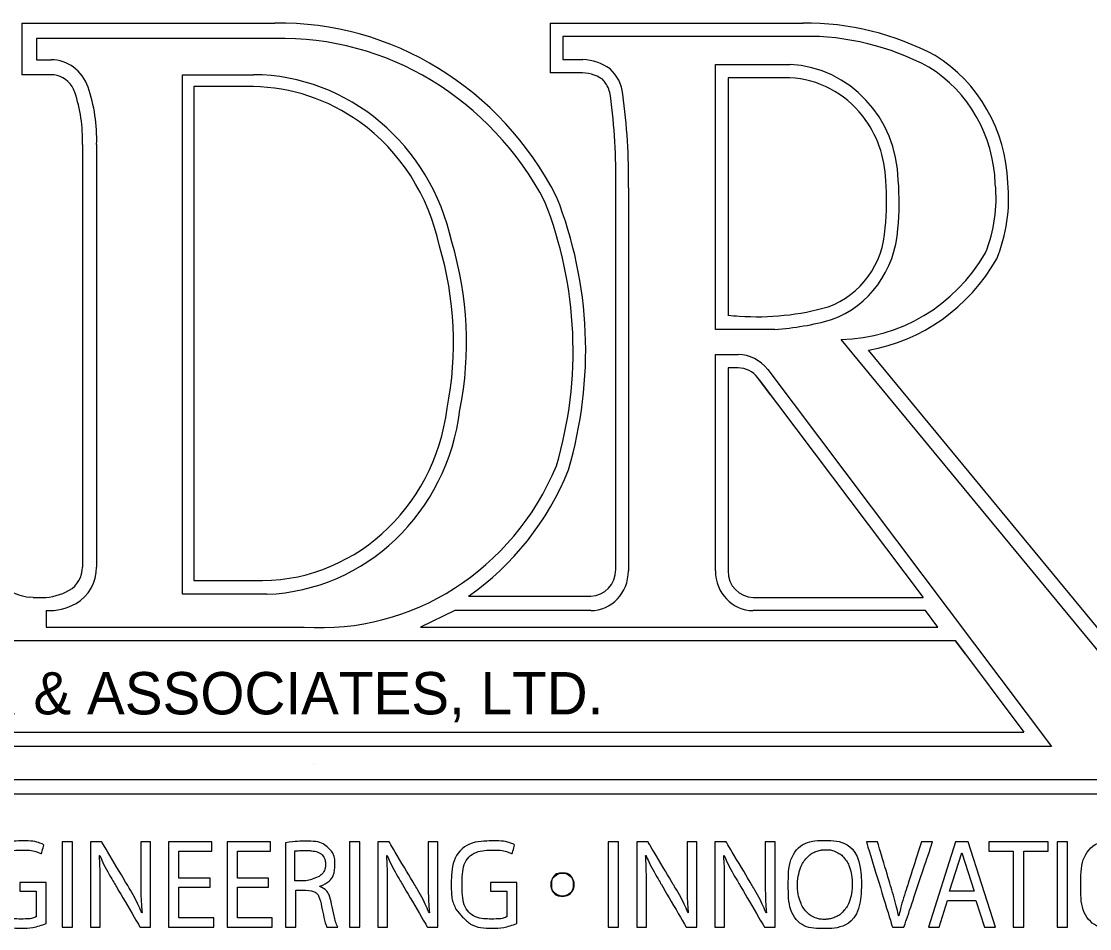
# Model space of a CAD drawing. Extents: x 0 to 34, y 0 to 22.
# Drawn here: x 32.53 to 33.336, y 3.375 to 4.06 of the extents above; entities that cross this region are included whole.
import ezdxf

# ---------------------------------------------------------------- set-up
doc = ezdxf.new("R2010")
doc.units = 0
doc.layers.add('SH_Data', color=7, linetype='Continuous')

msp = doc.modelspace()

# ---------------------------------------------------------------- linework, layer by layer
at = {"layer": 'SH_Data'}
for p, q in [((32.52996, 4.059), (32.52996, 4.02001)), ((32.52996, 4.059), (32.72096, 4.059)), ((32.92896, 4.059), (32.92896, 4.02146)), ((32.92896, 4.059), (33.11996, 4.059)), ((32.92896, 4.059), (32.92896, 4.02146)), ((32.92896, 4.059), (33.11996, 4.059)), ((32.54419, 4.02001), (32.52996, 4.02001)), ((32.55198, 4.02001), (32.54419, 4.02001)), ((32.94319, 4.02146), (32.92896, 4.02146)), ((32.94319, 4.02146), (32.92896, 4.02146)), ((32.95098, 4.02146), (32.94319, 4.02146)), ((32.70486, 4.01101), (32.65976, 4.01101)), ((32.65976, 4.01101), (32.65976, 3.63792)), ((32.57566, 3.96729), (32.57566, 3.64811)), ((32.97852, 3.64621), (32.97852, 3.93474)), ((33.38489, 3.55057), (33.16923, 3.81191)), ((33.08681, 3.78957), (33.2106, 3.62519)), ((32.65976, 3.63792), (32.66831, 3.63792)), ((32.66831, 3.63792), (32.70486, 3.63792)), ((32.53838, 3.62516), (32.53558, 3.62542)), ((32.53838, 3.62516), (32.53558, 3.62542)), ((32.53838, 3.62516), (32.54534, 3.62516)), ((32.86732, 3.62621), (32.95952, 3.62621)), ((33.08223, 3.62519), (33.2106, 3.62519)), ((33.23507, 3.59224), (33.28673, 3.52336)), ((32.21118, 3.52336), (33.28673, 3.52336)), ((32.75, 3.5), (32.75, 3.5)), ((33.44039, 3.47664), (32.07007, 3.47664)), ((32.7567, 3.4307), (32.75677, 3.43063)), ((33.2306, 3.40329), (33.23982, 3.43225)), ((33.23982, 3.43225), (33.24908, 3.40329)), ((32.75255, 3.4136), (32.74792, 3.41193)), ((32.73689, 3.41095), (32.73609, 3.41095)), ((32.74792, 3.41193), (32.74453, 3.41095)), ((32.75492, 3.40673), (32.75492, 3.40702)), ((33.24908, 3.40329), (33.2306, 3.40329)), ((32.76039, 3.376), (32.76847, 3.376))]:
    msp.add_line(p, q, dxfattribs=at)
for points in [[(32.72096, 4.04743), (32.54097, 4.04743), (32.54097, 4.03132), (32.55198, 4.03132)], [(33.11996, 4.049), (32.93846, 4.049), (32.93846, 4.03146), (32.95356, 4.03146)], [(33.05373, 4.02776), (33.11024, 4.02776)], [(33.09871, 3.82764), (33.05373, 3.82764), (33.05373, 4.02776)], [(32.65139, 3.62757), (32.65139, 4.02001), (32.70486, 4.02001)], [(33.11001, 4.01776), (33.06323, 4.01776), (33.06323, 3.83841)], [(32.58641, 3.96729), (32.58641, 3.96683), (32.58641, 3.64811)], [(32.98802, 3.93464), (32.98802, 3.64519)], [(33.37719, 3.54313), (33.14872, 3.82)], [(33.05373, 3.64519), (33.05373, 3.80857), (33.07085, 3.80857)], [(33.09319, 3.79721), (33.30749, 3.51264), (32.20382, 3.51264)], [(33.07085, 3.79857), (33.06323, 3.79857), (33.06323, 3.64519)], [(33.09537, 3.77821), (33.08574, 3.791)], [(32.71502, 3.62757), (32.65139, 3.62757)], [(32.86732, 3.62621), (32.88937, 3.62621)], [(33.08223, 3.62519), (33.08603, 3.62519)], [(32.54836, 3.61524), (32.54836, 3.60274), (32.74315, 3.60274)], [(32.95952, 3.61519), (32.85698, 3.61519), (32.83108, 3.60274), (33.22168, 3.60274), (33.21235, 3.61519), (33.08223, 3.61519)], [(33.24257, 3.58224), (33.23507, 3.59224), (32.24118, 3.59224), (32.20224, 3.52719)], [(32.06602, 3.50059), (32.06602, 3.48764), (33.42994, 3.48764), (33.42994, 3.50061)], [(32.72909, 3.43966), (32.72909, 3.376), (32.73689, 3.376), (32.73689, 3.40395), (32.74425, 3.40395)], [(33.25036, 3.39629), (33.25682, 3.376), (33.26516, 3.376), (33.24452, 3.44052), (33.23511, 3.44052), (33.21456, 3.376), (33.22263, 3.376), (33.22891, 3.39629), (33.25036, 3.39629)], [(32.74453, 3.41095), (32.74439, 3.41095), (32.74425, 3.41095)]]:
    msp.add_lwpolyline(points, dxfattribs=at)
msp.add_circle((32.93824, 3.40825), 0.00867, dxfattribs=at)
for centre, major_axis, start_param, end_param in [((32.72433, 3.80818), (0, 0.25085), 5.209873, 6.297313), ((33.12226, 3.8329), (0, 0.22611), 5.810103, 6.294452), ((33.12226, 3.8329), (0, 0.22611), 5.810103, 6.294452), ((32.72602, 3.80812), (0, 0.23937), 5.218006, 6.305445), ((33.12243, 3.83351), (0, 0.21551), 5.814829, 6.29527), ((33.16379, 3.93362), (0, 0.11672), 4.753214, 5.755325), ((33.16379, 3.93362), (0, 0.11672), 4.753214, 5.755325), ((32.55198, 4.00001), (0, 0.03131), 5.060756, 6.283185), ((32.95218, 3.98966), (0, 0.04182), 5.696071, 6.248499), ((33.10631, 3.93781), (0, 0.09005), 4.740194, 6.23721), ((33.16379, 3.93362), (0, 0.10672), 4.750292, 5.755325), ((32.55198, 4.00001), (0, 0.02), 5.294753, 6.283185), ((32.70388, 3.8572), (0, 0.16282), 4.938334, 6.276888), ((32.95218, 3.98966), (0, 0.03182), 5.717883, 6.322951), ((32.95511, 4.00164), (0, 0.03041), 4.832872, 5.561833), ((33.10631, 3.93781), (0, 0.08005), 5.402738, 6.234422), ((32.55198, 4.00001), (0, 0.02), 5.060756, 5.294753), ((32.47755, 3.97156), (0, 0.11467), 4.675194, 5.060756), ((32.70276, 3.85737), (0, 0.15366), 5.684676, 6.268828), ((32.95511, 4.00164), (0, 0.02041), 5.34604, 5.529903), ((32.95511, 4.00164), (0, 0.02041), 4.827568, 5.34604), ((32.95511, 4.00164), (0, 0.02041), 4.827568, 5.34604), ((32.47755, 3.97156), (0, 0.10336), 4.671123, 5.060756), ((32.57484, 3.94271), (0, 0.425), 4.693619, 4.857063), ((32.57484, 3.94271), (0, 0.425), 4.693619, 4.857063), ((32.57484, 3.94271), (0, 0.435), 4.693836, 4.856756), ((33.10631, 3.93781), (0, 0.08005), 4.740194, 5.402738), ((33.10631, 3.93781), (0, 0.08005), 4.740194, 5.402738), ((32.70276, 3.85737), (0, 0.15366), 4.930275, 5.684676), ((33.00347, 3.92393), (0, 0.18895), 4.608112, 4.797709), ((33.00347, 3.92393), (0, 0.18895), 4.608112, 4.797709), ((33.00861, 3.92385), (0, 0.19356), 4.607961, 4.797558), ((33.16601, 3.92655), (0, 0.10489), 4.309756, 4.818512), ((33.16601, 3.92655), (0, 0.11489), 4.303317, 4.815541), ((33.16601, 3.92655), (0, 0.11489), 4.303317, 4.815541), ((32.66751, 3.81165), (0, 0.2934), 4.410917, 5.105556), ((32.66751, 3.81165), (0, 0.3034), 4.410917, 5.105556), ((33.11824, 3.90826), (0, -0.06723), 0.330696, 1.511334), ((33.11824, 3.90826), (0, -0.06723), 0.330696, 1.511334), ((33.11779, 3.90865), (0, -0.07773), 0.32607, 1.506707), ((32.62458, 3.81762), (0, 0.24352), 4.507644, 5.016706), ((32.62601, 3.8177), (0, 0.25236), 4.509144, 5.018206), ((33.14666, 3.95705), (0, -0.13706), 0.015856, 1.021186), ((33.14666, 3.95705), (0, -0.14706), 0.16231, 1.026165), ((33.14666, 3.95705), (0, -0.14706), 0.16231, 1.026165), ((33.08509, 4.05603), (0, -0.21884), 6.219099, 6.545404), ((33.08509, 4.05603), (0, -0.21884), 6.219099, 6.545404), ((33.08509, 4.05603), (0, -0.21884), 6.177822, 6.219099), ((33.08509, 4.05603), (0, -0.22884), 0.06267, 0.262218), ((33.07085, 3.77857), (0, 0.03), 5.382662, 6.283185), ((33.07085, 3.77857), (0, 0.02), 5.382662, 6.283185), ((32.70994, 3.78768), (0, -0.14986), 6.247489, 7.723), ((32.70994, 3.78768), (0, -0.16019), 0.033392, 1.439815), ((32.75571, 3.80698), (0, -0.20467), 6.218561, 7.439351), ((32.75561, 3.80484), (0, -0.21386), 0.582172, 1.170799), ((32.55666, 3.64811), (0, -0.02), 0.497877, 1.570796), ((32.55666, 3.64811), (0, -0.03132), 0.497877, 1.570796), ((32.95952, 3.64621), (0, -0.02), 0, 1.570796), ((32.95952, 3.64519), (0, -0.03), 0, 1.570796), ((33.08223, 3.64519), (0, -0.03), 4.712389, 6.283185), ((33.08223, 3.64519), (0, -0.02), 4.712389, 6.283185), ((32.54013, 3.66951), (0, -0.04436), 5.785308, 6.174936), ((32.54561, 3.66951), (0, -0.04436), 6.276852, 6.781063), ((32.5506, 3.65985), (0, -0.04467), 6.230381, 6.780961)]:
    msp.add_ellipse(centre, major_axis=major_axis, ratio=0.95, start_param=start_param, end_param=end_param, dxfattribs=at)
for points, degree in [([(32.54839, 3.37887), (32.54489, 3.37753), (32.53798, 3.37533), (32.52982, 3.37533), (32.52067, 3.37533), (32.51313, 3.37782), (32.50721, 3.38385), (32.50201, 3.38921), (32.49878, 3.39783), (32.49878, 3.40788), (32.49887, 3.42712), (32.51125, 3.44119), (32.53152, 3.44119), (32.53852, 3.44119), (32.54399, 3.43956), (32.5466, 3.43822), (32.5466, 3.43822), (32.54471, 3.43142), (32.54471, 3.43142), (32.54148, 3.43295), (32.53745, 3.4342), (32.53134, 3.4342), (32.51663, 3.4342), (32.50703, 3.42444), (32.50703, 3.40826), (32.50703, 3.39189), (32.51627, 3.38222), (32.53036, 3.38222), (32.53547, 3.38222), (32.53897, 3.38299), (32.54077, 3.38395), (32.54077, 3.38395), (32.54077, 3.40319), (32.54077, 3.40319), (32.54077, 3.40319), (32.52847, 3.40319), (32.52847, 3.40319), (32.52847, 3.40319), (32.52847, 3.40989), (32.52847, 3.40989), (32.52847, 3.40989), (32.54839, 3.40989), (32.54839, 3.40989), (32.54839, 3.40989), (32.54839, 3.37887), (32.54839, 3.37887)], 3), ([(32.56813, 3.44052), (32.56813, 3.44052), (32.56813, 3.376), (32.56813, 3.376), (32.56813, 3.376), (32.56032, 3.376), (32.56032, 3.376), (32.56032, 3.376), (32.56032, 3.44052), (32.56032, 3.44052), (32.56032, 3.44052), (32.56813, 3.44052), (32.56813, 3.44052)], 3), ([(32.58177, 3.376), (32.58177, 3.376), (32.58177, 3.44052), (32.58177, 3.44052), (32.58177, 3.44052), (32.59029, 3.44052), (32.59029, 3.44052), (32.59029, 3.44052), (32.60967, 3.40788), (32.60967, 3.40788), (32.61416, 3.40031), (32.61766, 3.39352), (32.62053, 3.38691), (32.62053, 3.38691), (32.62071, 3.38701), (32.62071, 3.38701), (32.61999, 3.39562), (32.61981, 3.40347), (32.61981, 3.41352), (32.61981, 3.41352), (32.61981, 3.44052), (32.61981, 3.44052), (32.61981, 3.44052), (32.62717, 3.44052), (32.62717, 3.44052), (32.62717, 3.44052), (32.62717, 3.376), (32.62717, 3.376), (32.62717, 3.376), (32.61927, 3.376), (32.61927, 3.376), (32.61927, 3.376), (32.60007, 3.40874), (32.60007, 3.40874), (32.59585, 3.41592), (32.59182, 3.42329), (32.58876, 3.43027), (32.58876, 3.43027), (32.5885, 3.43018), (32.5885, 3.43018), (32.58894, 3.42204), (32.58912, 3.41429), (32.58912, 3.40357), (32.58912, 3.40357), (32.58912, 3.376), (32.58912, 3.376), (32.58912, 3.376), (32.58177, 3.376), (32.58177, 3.376)], 3), ([(32.67211, 3.40625), (32.67211, 3.40625), (32.64861, 3.40625), (32.64861, 3.40625), (32.64861, 3.40625), (32.64861, 3.38299), (32.64861, 3.38299), (32.64861, 3.38299), (32.67481, 3.38299), (32.67481, 3.38299), (32.67481, 3.38299), (32.67481, 3.376), (32.67481, 3.376), (32.67481, 3.376), (32.6408, 3.376), (32.6408, 3.376), (32.6408, 3.376), (32.6408, 3.44052), (32.6408, 3.44052), (32.6408, 3.44052), (32.67346, 3.44052), (32.67346, 3.44052), (32.67346, 3.44052), (32.67346, 3.43353), (32.67346, 3.43353), (32.67346, 3.43353), (32.64861, 3.43353), (32.64861, 3.43353), (32.64861, 3.43353), (32.64861, 3.41314), (32.64861, 3.41314), (32.64861, 3.41314), (32.67211, 3.41314), (32.67211, 3.41314), (32.67211, 3.41314), (32.67211, 3.40625), (32.67211, 3.40625)], 3), ([(32.71626, 3.40625), (32.71626, 3.40625), (32.69275, 3.40625), (32.69275, 3.40625), (32.69275, 3.40625), (32.69275, 3.38299), (32.69275, 3.38299), (32.69275, 3.38299), (32.71895, 3.38299), (32.71895, 3.38299), (32.71895, 3.38299), (32.71895, 3.376), (32.71895, 3.376), (32.71895, 3.376), (32.68494, 3.376), (32.68494, 3.376), (32.68494, 3.376), (32.68494, 3.44052), (32.68494, 3.44052), (32.68494, 3.44052), (32.7176, 3.44052), (32.7176, 3.44052), (32.7176, 3.44052), (32.7176, 3.43353), (32.7176, 3.43353), (32.7176, 3.43353), (32.69275, 3.43353), (32.69275, 3.43353), (32.69275, 3.43353), (32.69275, 3.41314), (32.69275, 3.41314), (32.69275, 3.41314), (32.71626, 3.41314), (32.71626, 3.41314), (32.71626, 3.41314), (32.71626, 3.40625), (32.71626, 3.40625)], 3), ([(32.75492, 3.40702), (32.76129, 3.40931), (32.76632, 3.41496), (32.76632, 3.42348), (32.76632, 3.42846), (32.76461, 3.43286), (32.76156, 3.43573), (32.7578, 3.43937), (32.75241, 3.44099), (32.74407, 3.44099), (32.73869, 3.44099), (32.73303, 3.44052), (32.72909, 3.43966)], 3), ([(32.78516, 3.44052), (32.78516, 3.44052), (32.78516, 3.376), (32.78516, 3.376), (32.78516, 3.376), (32.77735, 3.376), (32.77735, 3.376), (32.77735, 3.376), (32.77735, 3.44052), (32.77735, 3.44052), (32.77735, 3.44052), (32.78516, 3.44052), (32.78516, 3.44052)], 3), ([(32.79879, 3.376), (32.79879, 3.376), (32.79879, 3.44052), (32.79879, 3.44052), (32.79879, 3.44052), (32.80732, 3.44052), (32.80732, 3.44052), (32.80732, 3.44052), (32.8267, 3.40788), (32.8267, 3.40788), (32.83118, 3.40031), (32.83468, 3.39352), (32.83755, 3.38691), (32.83755, 3.38691), (32.83774, 3.38701), (32.83774, 3.38701), (32.83702, 3.39562), (32.83684, 3.40347), (32.83684, 3.41352), (32.83684, 3.41352), (32.83684, 3.44052), (32.83684, 3.44052), (32.83684, 3.44052), (32.84419, 3.44052), (32.84419, 3.44052), (32.84419, 3.44052), (32.84419, 3.376), (32.84419, 3.376), (32.84419, 3.376), (32.8363, 3.376), (32.8363, 3.376), (32.8363, 3.376), (32.8171, 3.40874), (32.8171, 3.40874), (32.81288, 3.41592), (32.80884, 3.42329), (32.80579, 3.43027), (32.80579, 3.43027), (32.80552, 3.43018), (32.80552, 3.43018), (32.80597, 3.42204), (32.80615, 3.41429), (32.80615, 3.40357), (32.80615, 3.40357), (32.80615, 3.376), (32.80615, 3.376), (32.80615, 3.376), (32.79879, 3.376), (32.79879, 3.376)], 3), ([(32.90386, 3.37887), (32.90036, 3.37753), (32.89345, 3.37533), (32.88529, 3.37533), (32.87613, 3.37533), (32.8686, 3.37782), (32.86267, 3.38385), (32.85747, 3.38921), (32.85424, 3.39783), (32.85424, 3.40788), (32.85433, 3.42712), (32.86671, 3.44119), (32.88699, 3.44119), (32.89399, 3.44119), (32.89946, 3.43956), (32.90206, 3.43822), (32.90206, 3.43822), (32.90018, 3.43142), (32.90018, 3.43142), (32.89695, 3.43295), (32.89291, 3.4342), (32.88681, 3.4342), (32.8721, 3.4342), (32.8625, 3.42444), (32.8625, 3.40826), (32.8625, 3.39189), (32.87174, 3.38222), (32.88582, 3.38222), (32.89094, 3.38222), (32.89444, 3.38299), (32.89623, 3.38395), (32.89623, 3.38395), (32.89623, 3.40319), (32.89623, 3.40319), (32.89623, 3.40319), (32.88394, 3.40319), (32.88394, 3.40319), (32.88394, 3.40319), (32.88394, 3.40989), (32.88394, 3.40989), (32.88394, 3.40989), (32.90386, 3.40989), (32.90386, 3.40989), (32.90386, 3.40989), (32.90386, 3.37887), (32.90386, 3.37887)], 3), ([(32.98065, 3.44052), (32.98065, 3.44052), (32.98065, 3.376), (32.98065, 3.376), (32.98065, 3.376), (32.97285, 3.376), (32.97285, 3.376), (32.97285, 3.376), (32.97285, 3.44052), (32.97285, 3.44052), (32.97285, 3.44052), (32.98065, 3.44052), (32.98065, 3.44052)], 3), ([(32.99429, 3.376), (32.99429, 3.376), (32.99429, 3.44052), (32.99429, 3.44052), (32.99429, 3.44052), (33.00282, 3.44052), (33.00282, 3.44052), (33.00282, 3.44052), (33.02219, 3.40788), (33.02219, 3.40788), (33.02668, 3.40031), (33.03018, 3.39352), (33.03305, 3.38691), (33.03305, 3.38691), (33.03323, 3.38701), (33.03323, 3.38701), (33.03251, 3.39562), (33.03234, 3.40347), (33.03234, 3.41352), (33.03234, 3.41352), (33.03234, 3.44052), (33.03234, 3.44052), (33.03234, 3.44052), (33.03969, 3.44052), (33.03969, 3.44052), (33.03969, 3.44052), (33.03969, 3.376), (33.03969, 3.376), (33.03969, 3.376), (33.03179, 3.376), (33.03179, 3.376), (33.03179, 3.376), (33.01259, 3.40874), (33.01259, 3.40874), (33.00838, 3.41592), (33.00434, 3.42329), (33.00129, 3.43027), (33.00129, 3.43027), (33.00102, 3.43018), (33.00102, 3.43018), (33.00147, 3.42204), (33.00165, 3.41429), (33.00165, 3.40357), (33.00165, 3.40357), (33.00165, 3.376), (33.00165, 3.376), (33.00165, 3.376), (32.99429, 3.376), (32.99429, 3.376)], 3), ([(33.05333, 3.376), (33.05333, 3.376), (33.05333, 3.44052), (33.05333, 3.44052), (33.05333, 3.44052), (33.06185, 3.44052), (33.06185, 3.44052), (33.06185, 3.44052), (33.08123, 3.40788), (33.08123, 3.40788), (33.08572, 3.40031), (33.08922, 3.39352), (33.09209, 3.38691), (33.09209, 3.38691), (33.09227, 3.38701), (33.09227, 3.38701), (33.09155, 3.39562), (33.09137, 3.40347), (33.09137, 3.41352), (33.09137, 3.41352), (33.09137, 3.44052), (33.09137, 3.44052), (33.09137, 3.44052), (33.09873, 3.44052), (33.09873, 3.44052), (33.09873, 3.44052), (33.09873, 3.376), (33.09873, 3.376), (33.09873, 3.376), (33.09083, 3.376), (33.09083, 3.376), (33.09083, 3.376), (33.07163, 3.40874), (33.07163, 3.40874), (33.06742, 3.41592), (33.06338, 3.42329), (33.06033, 3.43027), (33.06033, 3.43027), (33.06006, 3.43018), (33.06006, 3.43018), (33.0605, 3.42204), (33.06069, 3.41429), (33.06069, 3.40357), (33.06069, 3.40357), (33.06069, 3.376), (33.06069, 3.376), (33.06069, 3.376), (33.05333, 3.376), (33.05333, 3.376)], 3), ([(33.16405, 3.40893), (33.16405, 3.42807), (33.15337, 3.44157), (33.13686, 3.44157), (33.12071, 3.44157), (33.10878, 3.42817), (33.10878, 3.40768), (33.10878, 3.38816), (33.11999, 3.37495), (33.13596, 3.37495), (33.15139, 3.37495), (33.16405, 3.38672), (33.16405, 3.40893)], 3), ([(33.18746, 3.376), (33.18746, 3.376), (33.16772, 3.44052), (33.16772, 3.44052), (33.16772, 3.44052), (33.17616, 3.44052), (33.17616, 3.44052), (33.17616, 3.44052), (33.18558, 3.40874), (33.18558, 3.40874), (33.18818, 3.40003), (33.19042, 3.39218), (33.19204, 3.38461), (33.19204, 3.38461), (33.19222, 3.38461), (33.19222, 3.38461), (33.19392, 3.39208), (33.19643, 3.40022), (33.19912, 3.40864), (33.19912, 3.40864), (33.20935, 3.44052), (33.20935, 3.44052), (33.20935, 3.44052), (33.2177, 3.44052), (33.2177, 3.44052), (33.2177, 3.44052), (33.19608, 3.376), (33.19608, 3.376), (33.19608, 3.376), (33.18746, 3.376), (33.18746, 3.376)], 3), ([(33.27862, 3.43343), (33.27862, 3.43343), (33.26023, 3.43343), (33.26023, 3.43343), (33.26023, 3.43343), (33.26023, 3.44052), (33.26023, 3.44052), (33.26023, 3.44052), (33.305, 3.44052), (33.305, 3.44052), (33.305, 3.44052), (33.305, 3.43343), (33.305, 3.43343), (33.305, 3.43343), (33.28652, 3.43343), (33.28652, 3.43343), (33.28652, 3.43343), (33.28652, 3.376), (33.28652, 3.376), (33.28652, 3.376), (33.27862, 3.376), (33.27862, 3.376), (33.27862, 3.376), (33.27862, 3.43343), (33.27862, 3.43343)], 3), ([(33.31953, 3.44052), (33.31953, 3.44052), (33.31953, 3.376), (33.31953, 3.376), (33.31953, 3.376), (33.31173, 3.376), (33.31173, 3.376), (33.31173, 3.376), (33.31173, 3.44052), (33.31173, 3.44052), (33.31173, 3.44052), (33.31953, 3.44052), (33.31953, 3.44052)], 3), ([(33.38485, 3.40893), (33.38485, 3.42807), (33.37417, 3.44157), (33.35766, 3.44157), (33.34151, 3.44157), (33.32958, 3.42817), (33.32958, 3.40768), (33.32958, 3.38816), (33.34079, 3.37495), (33.35676, 3.37495), (33.3722, 3.37495), (33.38485, 3.38672), (33.38485, 3.40893)], 3), ([(32.73609, 3.43362), (32.73819, 3.43382), (32.74049, 3.43395), (32.74305, 3.43399), (32.74347, 3.43399), (32.74389, 3.43399), (32.74418, 3.43399), (32.74436, 3.43399), (32.74517, 3.43399), (32.74579, 3.43397), (32.74756, 3.43389), (32.74862, 3.43379), (32.75147, 3.43338), (32.75291, 3.43296), (32.75514, 3.43198), (32.75595, 3.43142), (32.7567, 3.4307)], 3), ([(32.73609, 3.41095), (32.73609, 3.41973), (32.73609, 3.42819), (32.73609, 3.43362)], 2), ([(32.75677, 3.43063), (32.75723, 3.4302), (32.75765, 3.42966), (32.7584, 3.42832), (32.75872, 3.42753), (32.75918, 3.4257), (32.75931, 3.42467), (32.75932, 3.42328), (32.75931, 3.42299), (32.75928, 3.42244), (32.75926, 3.42218), (32.75917, 3.42141), (32.75908, 3.42093), (32.75853, 3.41869), (32.75773, 3.41734), (32.75557, 3.41508), (32.75417, 3.41418), (32.75255, 3.4136)], 3), ([(33.11577, 3.40768), (33.11577, 3.41212), (33.11642, 3.41606), (33.11865, 3.42278), (33.12022, 3.42557), (33.12398, 3.43001), (33.12616, 3.43167), (33.12983, 3.43338), (33.13113, 3.43382), (33.13319, 3.43426), (33.13389, 3.43438), (33.13498, 3.43449), (33.13535, 3.43452), (33.1361, 3.43456), (33.13646, 3.43457), (33.14003, 3.43457), (33.14273, 3.43394), (33.14745, 3.43172), (33.14948, 3.43012), (33.15298, 3.42586), (33.15443, 3.42318), (33.15647, 3.41678), (33.15705, 3.41306), (33.15705, 3.40893)], 3), ([(32.94657, 3.40825), (32.94657, 3.40347), (32.94284, 3.39958), (32.93824, 3.39958), (32.93363, 3.39958), (32.92991, 3.40347), (32.92991, 3.40825), (32.92991, 3.41304), (32.93363, 3.41693), (32.93824, 3.41693), (32.94284, 3.41693), (32.94657, 3.41304), (32.94657, 3.40825)], 3), ([(32.74425, 3.41095), (32.74421, 3.41095), (32.73693, 3.41095), (32.73689, 3.41095)], 2), ([(32.76847, 3.376), (32.76721, 3.37849), (32.76578, 3.38471), (32.76381, 3.39371), (32.76237, 3.40041), (32.75959, 3.405), (32.75492, 3.40673)], 3), ([(33.15705, 3.40893), (33.15705, 3.40404), (33.15635, 3.39991), (33.15404, 3.39307), (33.15244, 3.39038), (33.14868, 3.38615), (33.14652, 3.38461), (33.14287, 3.38303), (33.14158, 3.38263), (33.13955, 3.38223), (33.13885, 3.38212), (33.13743, 3.38198), (33.13672, 3.38195), (33.13293, 3.38195), (33.13029, 3.38256), (33.1256, 3.38476), (33.12353, 3.38635), (33.11997, 3.39061), (33.11848, 3.39329), (33.11638, 3.39972), (33.11577, 3.40347), (33.11577, 3.40768)], 3), ([(32.74425, 3.40395), (32.75133, 3.40366), (32.75457, 3.40031), (32.75636, 3.39141), (32.75806, 3.38337), (32.75941, 3.37792), (32.76039, 3.376)], 3)]:
    msp.add_open_spline(points, degree=degree, dxfattribs=at)

# ---------------------------------------------------------------- texts
msp.add_text('ADR & ASSOCIATES, LTD.', height=0.0319999, rotation=360, dxfattribs=at).set_placement((32.43646, 3.5368))

doc.saveas('drawing.dxf')
